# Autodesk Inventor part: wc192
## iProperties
Shininess: 64.0
Length Units: 11272
Angle Units: 11279
Time Units: 11290
Mass Units: 11286
Length Display Precision: 3
Angle Display Precision: 2
Compacted: True
Part Number: wc192
Document SubType Name: Modeling
Created: 2004-08
Designer: John Blackburn
Manufacturer: Standard
Standards Organization: Custom
Material: Phenolic
Density: 0.0
Volumn: 0.0
Area: 0.0
PropertySet Name: Model Information
Control State: 0
Master: False
Checked Out: False
Author: John Blackburn
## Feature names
1. Base1
